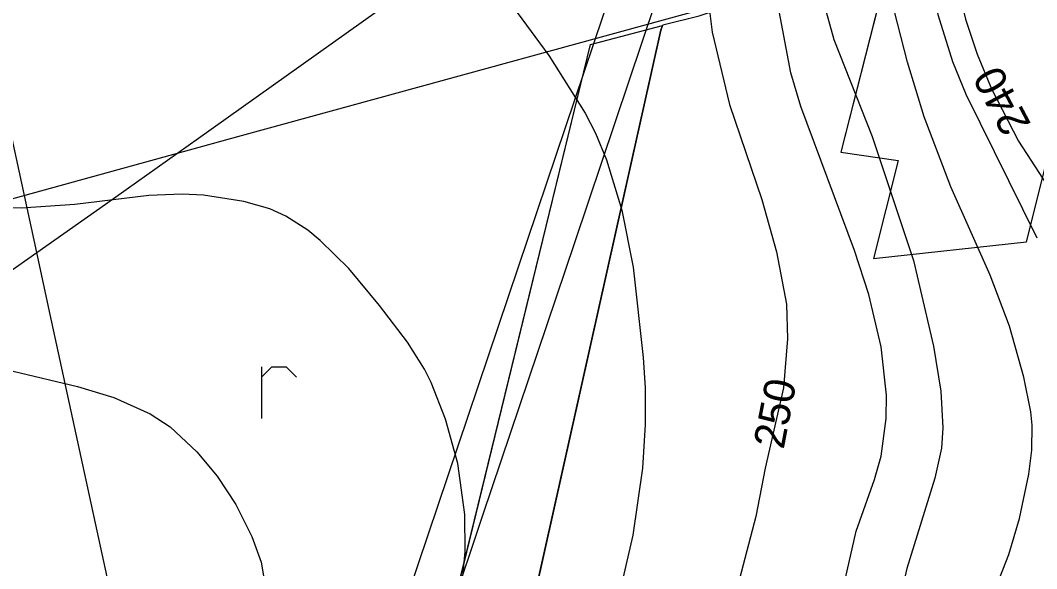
# Model space of a CAD drawing. Extents: x -662620 to -656370, y -1067090 to -1062990.
# Drawn here: x -658438.7 to -658005.3, y -1065680.9 to -1065447 of the extents above; entities that cross this region are included whole.
import ezdxf

# ---------------------------------------------------------------- set-up
doc = ezdxf.new("R2010")
doc.units = 0
for name, color, linetype in [('Agrotechnicka_opatreni_hrazkovani_a_dulkovani__mulcovani', 7, 'Continuous'), ('ELEK__VEDENÍ_VN_-_NADZEMNÍ', 7, 'Continuous'), ('ELEK__VEDENÍ_VVN_-_NADZEMNÍ', 7, 'Continuous'), ('ORNÁ_PŮDA_-_ZNAČKA', 7, 'Continuous'), ('OVOCNÝ_SAD_-_NAVRŽENÝ', 7, 'Continuous'), ('VRSTEVNICE_ZDŮRAZNĚNÁ', 7, 'Continuous'), ('VRSTEVNICE_ZDŮRAZNĚNÁ_-_POPIS', 7, 'Continuous'), ('VRSTEVNICE_ZÁKLADNÍ', 7, 'Continuous')]:
    doc.layers.add(name, color=color, linetype=linetype)

msp = doc.modelspace()

# ---------------------------------------------------------------- linework, layer by layer
at = {"layer": 'Agrotechnicka_opatreni_hrazkovani_a_dulkovani__mulcovani'}
msp.add_lwpolyline([(-658442.44, -1065523.3), (-658443.3, -1065431.9), (-658351.8, -1065406.5), (-658174.8, -1065352.7), (-658175.8, -1065348.4), (-658137.9, -1065336.7), (-658101.39, -1065325.05), (-657977.61, -1065291.39), (-657955.7, -1065285), (-657886.54, -1065253.17), (-657902.2, -1065289.3), (-657944.34, -1065374.26), (-657952.2, -1065387.5), (-657958.74, -1065388.45), (-657979.2, -1065393.9), (-658107.1, -1065431), (-658344.5, -1065496.2)], close=True, dxfattribs=at)
at = {"layer": 'ELEK__VEDENÍ_VN_-_NADZEMNÍ'}
for points in [[(-658431.73, -1065546.01), (-658474.41, -1065349.27), (-658523.9, -1065120.81)], [(-658431.73, -1065546.01), (-658402.37, -1065525.35), (-658362.82, -1065497.28), (-658280.56, -1065438.78), (-658207.8, -1065387.04), (-658166.37, -1065373.74)], [(-659283.51, -1066152.49), (-659200.82, -1066093.95), (-659094.6, -1066018.18), (-659022.28, -1065966.69), (-658937.63, -1065906.48), (-658856.53, -1065848.35), (-658776.07, -1065791.16), (-658693.11, -1065732.39), (-658614.47, -1065676.12), (-658531.84, -1065617.27), (-658444.6, -1065555.07), (-658431.73, -1065546.01)], [(-658329.68, -1066275.66), (-658331.53, -1066007.67), (-658377.43, -1065796.27), (-658425.98, -1065572.49), (-658431.73, -1065546.01)]]:
    msp.add_lwpolyline(points, dxfattribs=at)
at = {"layer": 'ELEK__VEDENÍ_VVN_-_NADZEMNÍ'}
for points in [[(-658143.6, -1065366.43), (-658167.84, -1065439.13), (-658202.48, -1065541.95), (-658241.62, -1065658.23), (-658283.03, -1065781.93), (-658282.55, -1065909.7), (-658281.02, -1066039.46), (-658280.08, -1066204), (-658279.27, -1066280.92)], [(-658166.37, -1065373.74), (-658226.48, -1065552.24), (-658303.49, -1065780.98), (-658301.72, -1066029.74), (-658299.99, -1066275.27)]]:
    msp.add_lwpolyline(points, dxfattribs=at)
at = {"layer": 'ORNÁ_PŮDA_-_ZNAČKA'}
for points in [[(-658335.89, -1065594.85), (-658335.89, -1065616.78)], [(-658335.89, -1065599.24), (-658331.51, -1065594.85)], [(-658331.51, -1065594.85), (-658325.37, -1065594.85)], [(-658325.37, -1065594.85), (-658320.98, -1065599.24)]]:
    msp.add_lwpolyline(points, dxfattribs=at)
at = {"layer": 'OVOCNÝ_SAD_-_NAVRŽENÝ'}
for p, q in [((-658067.9, -1065421.1), (-658088.9, -1065503.2)), ((-658164.8, -1065448.9), (-658149.3, -1065445)), ((-658221.5, -1065701.5), (-658165.55, -1065451.1)), ((-658165.55, -1065451.1), (-658221.5, -1065701.5)), ((-658195.57, -1065457.3), (-658164.91, -1065449.23)), ((-658165.55, -1065451.1), (-658164.91, -1065449.23)), ((-658164.91, -1065449.23), (-658165.55, -1065451.1)), ((-658164.91, -1065449.23), (-658164.8, -1065448.9)), ((-658253.71, -1065695.6), (-658195.57, -1065457.3)), ((-658088.9, -1065503.2), (-658064.4, -1065506.7)), ((-658009.6, -1065541.5), (-657999.43, -1065500.58)), ((-658064.4, -1065506.7), (-658074.9, -1065548.6)), ((-658074.9, -1065548.6), (-658009.6, -1065541.5))]:
    msp.add_line(p, q, dxfattribs=at)
msp.add_lwpolyline([(-658221.5, -1065701.5), (-658165.55, -1065451.1), (-658164.91, -1065449.23), (-658164.8, -1065448.9), (-658149.3, -1065445), (-658107.1, -1065431), (-658067.9, -1065421.1), (-658088.9, -1065503.2), (-658064.4, -1065506.7), (-658074.9, -1065548.6), (-658009.6, -1065541.5), (-657999.43, -1065500.58)], dxfattribs=at)
msp.add_lwpolyline([(-658301.84, -1065892.39), (-658301.9, -1065892.6), (-658310.7, -1065890.7), (-658259, -1065694.5), (-658253.71, -1065695.6), (-658195.57, -1065457.3), (-658164.91, -1065449.23), (-658165.55, -1065451.1), (-658221.5, -1065701.5), (-658243.92, -1065697.43), (-658244.07, -1065697.41), (-658251.21, -1065696.07), (-658302.7, -1065892.3)], close=True, dxfattribs=at)
at = {"layer": 'VRSTEVNICE_ZDŮRAZNĚNÁ'}
for points in [[(-657980.36, -1065348.32), (-658007.8, -1065363.04), (-658014.66, -1065367.61), (-658026.38, -1065377.05), (-658030.96, -1065382.19), (-658036.39, -1065391.62), (-658039.82, -1065403.92), (-658040.82, -1065412.78), (-658040.1, -1065427.93), (-658035.67, -1065446.51), (-658030.67, -1065461.38), (-658024.53, -1065476.24), (-658013.09, -1065498.54), (-657976.5, -1065554.85)], [(-658145.88, -1065434.79), (-658143.73, -1065451.94), (-658136.3, -1065482.82), (-658122.58, -1065523.41), (-658116.29, -1065545.71), (-658112, -1065568), (-658111.57, -1065582.87), (-658113.29, -1065603.74), (-658121.15, -1065638.04), (-658125.15, -1065658.62), (-658147.59, -1065744.38)]]:
    msp.add_lwpolyline(points, dxfattribs=at)
at = {"layer": 'VRSTEVNICE_ZÁKLADNÍ'}
for points in [[(-657989.79, -1065341.74), (-658011.8, -1065352.32), (-658019.81, -1065356.89), (-658028.81, -1065363.47), (-658037.1, -1065371.47), (-658042.68, -1065378.33), (-658046.68, -1065387.19), (-658049.25, -1065396.48), (-658050.82, -1065410.49), (-658049.54, -1065434.5), (-658047.54, -1065444.51), (-658041.25, -1065464.52), (-658035.53, -1065478.53), (-658005.23, -1065539.7)], [(-657989.79, -1065341.74), (-658011.8, -1065352.32), (-658019.81, -1065356.89), (-658028.81, -1065363.47), (-658037.1, -1065371.47), (-658042.68, -1065378.33), (-658046.68, -1065387.19), (-658049.25, -1065396.48), (-658050.82, -1065410.49), (-658049.54, -1065434.5), (-658047.54, -1065444.51), (-658041.25, -1065464.52), (-658035.53, -1065478.53), (-658005.23, -1065539.7)], [(-658451.75, -1065447.37), (-658425.17, -1065436.36), (-658367.42, -1065415.35), (-658351.41, -1065411.06), (-658339.41, -1065408.92), (-658329.4, -1065408.06), (-658302.53, -1065408.49), (-658268.51, -1065413.35), (-658258.22, -1065415.92), (-658247.93, -1065421.93), (-658235.35, -1065433.5), (-658226.92, -1065443.65), (-658213.34, -1065461.95), (-658197.9, -1065486.53), (-658193.47, -1065495.11), (-658188.76, -1065506.54), (-658182.18, -1065527.98), (-658177.46, -1065552.28), (-658173.18, -1065590.87), (-658172.32, -1065603.74), (-658172.32, -1065619.46), (-658173.46, -1065638.04), (-658177.61, -1065666.63), (-658184.75, -1065698.07)], [(-658451.75, -1065447.37), (-658425.17, -1065436.36), (-658367.42, -1065415.35), (-658351.41, -1065411.06), (-658339.41, -1065408.92), (-658329.4, -1065408.06), (-658302.53, -1065408.49), (-658268.51, -1065413.35), (-658258.22, -1065415.92), (-658247.93, -1065421.93), (-658235.35, -1065433.5), (-658226.92, -1065443.65), (-658213.34, -1065461.95), (-658197.9, -1065486.53), (-658193.47, -1065495.11), (-658188.76, -1065506.54), (-658182.18, -1065527.98), (-658177.46, -1065552.28), (-658173.18, -1065590.87), (-658172.32, -1065603.74), (-658172.32, -1065619.46), (-658173.46, -1065638.04), (-658177.61, -1065666.63), (-658184.75, -1065698.07)], [(-658086.84, -1065684.92), (-658082.27, -1065664.91), (-658074.55, -1065642.9), (-658071.69, -1065632.9), (-658069.55, -1065616.89), (-658069.41, -1065606.88), (-658071.69, -1065586.3), (-658076.84, -1065564), (-658082.98, -1065545.13), (-658105.85, -1065483.67), (-658110.14, -1065469.38), (-658115.57, -1065440.79)], [(-658086.84, -1065684.92), (-658082.27, -1065664.91), (-658074.55, -1065642.9), (-658071.69, -1065632.9), (-658069.55, -1065616.89), (-658069.41, -1065606.88), (-658071.69, -1065586.3), (-658076.84, -1065564), (-658082.98, -1065545.13), (-658105.85, -1065483.67), (-658110.14, -1065469.38), (-658115.57, -1065440.79)], [(-658095.85, -1065440.79), (-658091.85, -1065455.09), (-658075.41, -1065496.54), (-658057.83, -1065549.42), (-658049.25, -1065586.01), (-658046.25, -1065605.17), (-658045.39, -1065620.89), (-658045.96, -1065629.46), (-658048.82, -1065642.33), (-658060.69, -1065680.92), (-658064.69, -1065698.07)], [(-658095.85, -1065440.79), (-658091.85, -1065455.09), (-658075.41, -1065496.54), (-658057.83, -1065549.42), (-658049.25, -1065586.01), (-658046.25, -1065605.17), (-658045.39, -1065620.89), (-658045.96, -1065629.46), (-658048.82, -1065642.33), (-658060.69, -1065680.92), (-658064.69, -1065698.07)], [(-658024.53, -1065693.78), (-658017.24, -1065674.92), (-658012.66, -1065659.48), (-658008.66, -1065640.61), (-658007.37, -1065630.32), (-658007.23, -1065619.75), (-658007.8, -1065614.03), (-658010.8, -1065599.16), (-658016.95, -1065577.44), (-658025.1, -1065555.71), (-658041.96, -1065517.98), (-658053.25, -1065488.1), (-658060.4, -1065464.81), (-658066.12, -1065442.65)], [(-658024.53, -1065693.78), (-658017.24, -1065674.92), (-658012.66, -1065659.48), (-658008.66, -1065640.61), (-658007.37, -1065630.32), (-658007.23, -1065619.75), (-658007.8, -1065614.03), (-658010.8, -1065599.16), (-658016.95, -1065577.44), (-658025.1, -1065555.71), (-658041.96, -1065517.98), (-658053.25, -1065488.1), (-658060.4, -1065464.81), (-658066.12, -1065442.65)], [(-658250.93, -1065693.21), (-658249.07, -1065673.77), (-658249.22, -1065657.77), (-658252.22, -1065636.04), (-658257.36, -1065617.17), (-658263.51, -1065601.45), (-658266.37, -1065595.73), (-658273.66, -1065584.3), (-658285.52, -1065568.58), (-658298.67, -1065552.85), (-658310.82, -1065540.85), (-658316.11, -1065536.56), (-658325.54, -1065530.55), (-658332.4, -1065527.41), (-658343.41, -1065524.27), (-658360.56, -1065521.55), (-658369.71, -1065521.12), (-658384, -1065521.69), (-658415.45, -1065525.55), (-658438.32, -1065527.12), (-658481.2, -1065526.84)], [(-658250.93, -1065693.21), (-658249.07, -1065673.77), (-658249.22, -1065657.77), (-658252.22, -1065636.04), (-658257.36, -1065617.17), (-658263.51, -1065601.45), (-658266.37, -1065595.73), (-658273.66, -1065584.3), (-658285.52, -1065568.58), (-658298.67, -1065552.85), (-658310.82, -1065540.85), (-658316.11, -1065536.56), (-658325.54, -1065530.55), (-658332.4, -1065527.41), (-658343.41, -1065524.27), (-658360.56, -1065521.55), (-658369.71, -1065521.12), (-658384, -1065521.69), (-658415.45, -1065525.55), (-658438.32, -1065527.12), (-658481.2, -1065526.84)], [(-658441.75, -1065596.59), (-658414.3, -1065603.16), (-658398.87, -1065607.88), (-658383.43, -1065614.89), (-658374.85, -1065620.46), (-658363.42, -1065631.04), (-658354.84, -1065641.47), (-658346.84, -1065653.48), (-658339.98, -1065667.2), (-658335.98, -1065678.2), (-658329.26, -1065718.65), (-658329.26, -1065729.8), (-658331.55, -1065750.1), (-658341.69, -1065800.13), (-658345.84, -1065827.28), (-658347.84, -1065845.87), (-658350.27, -1065888.6), (-658352.7, -1065897.89), (-658356.84, -1065907.9), (-658373.28, -1065935.91), (-658379.28, -1065950.21), (-658381.54, -1065958.04)], [(-658441.75, -1065596.59), (-658414.3, -1065603.16), (-658398.87, -1065607.88), (-658383.43, -1065614.89), (-658374.85, -1065620.46), (-658363.42, -1065631.04), (-658354.84, -1065641.47), (-658346.84, -1065653.48), (-658339.98, -1065667.2), (-658335.98, -1065678.2), (-658329.26, -1065718.65), (-658329.26, -1065729.8), (-658331.55, -1065750.1), (-658341.69, -1065800.13), (-658345.84, -1065827.28), (-658347.84, -1065845.87), (-658350.27, -1065888.6), (-658352.7, -1065897.89), (-658356.84, -1065907.9), (-658373.28, -1065935.91), (-658379.28, -1065950.21), (-658381.54, -1065958.04)]]:
    msp.add_lwpolyline(points, dxfattribs=at)

# ---------------------------------------------------------------- texts
at = {"layer": 'VRSTEVNICE_ZDŮRAZNĚNÁ_-_POPIS'}
for s, rotation, p in [('240', 117.9, (-658007.52, -1065491.34)), ('250', 79.2, (-658113.24, -1065630.3))]:
    msp.add_text(s, height=13.2, rotation=rotation, dxfattribs=at).set_placement(p)

doc.saveas('drawing.dxf')
